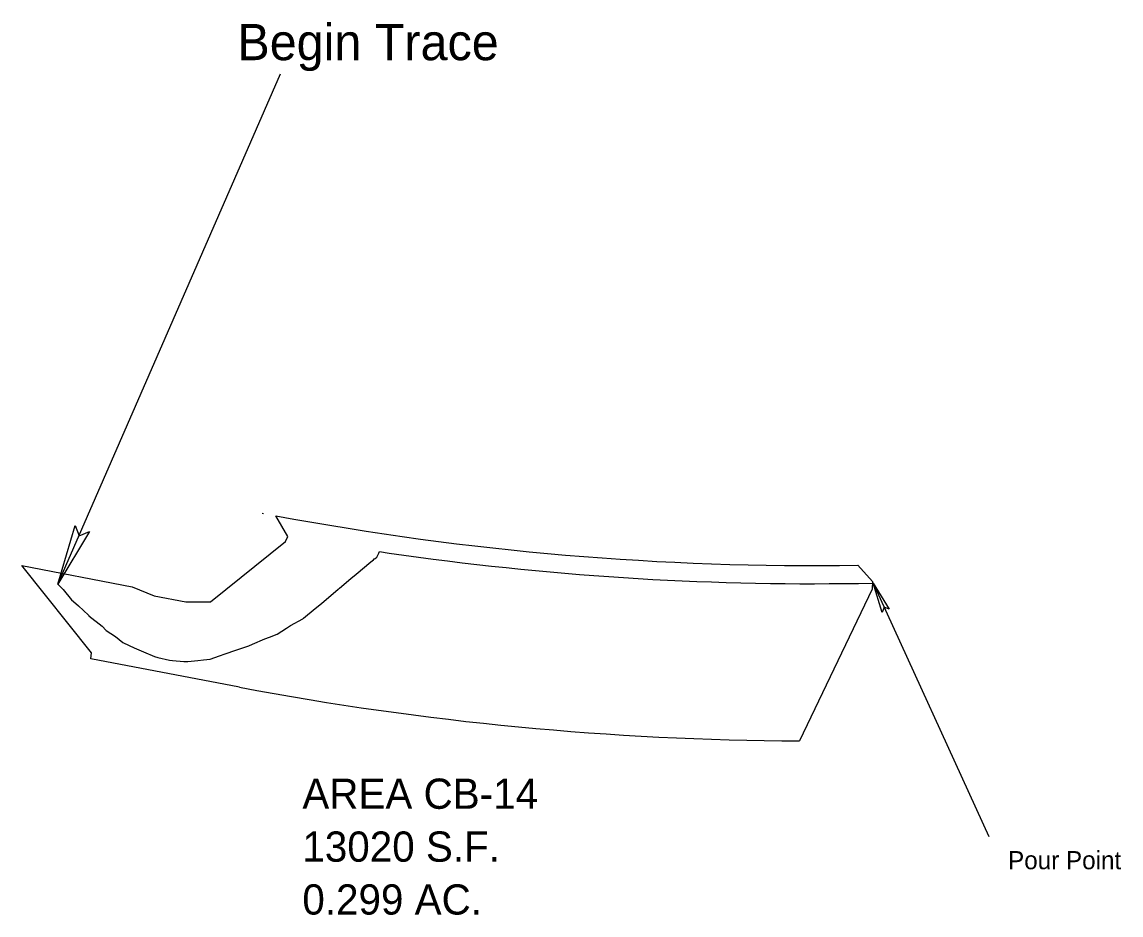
# Model space of a CAD drawing. Extents: x 3678 to 4042, y 2939 to 3235.
import ezdxf

# ---------------------------------------------------------------- set-up
doc = ezdxf.new("R2010")
doc.units = 0
for name, color, linetype in [('Default', 7, 'Continuous'), ('DESIGN - SCRATCH - User 1', 7, 'Continuous'), ('SURVEY - CENTERLINE - Preliminary', 7, 'Continuous'), ('SURVEY - CENTERLINE - Preliminary Text', 7, 'Continuous'), ('SURVEY - DRAINAGE - Area Shapes', 7, 'Continuous')]:
    doc.layers.add(name, color=color, linetype=linetype)

msp = doc.modelspace()

# ---------------------------------------------------------------- linework, layer by layer
at = {"layer": 'DESIGN - SCRATCH - User 1'}
msp.add_line((3960.18, 3049.18), (3998.4, 2965.35), dxfattribs=at)
msp.add_lwpolyline([(3960.18, 3049.18), (3965.48, 3040.55), (3963.81, 3041.22), (3963.16, 3039.49)], close=True, dxfattribs=at)
msp.add_lwpolyline([(3960.18, 3049.18), (3965.48, 3040.55), (3963.81, 3041.22), (3963.16, 3039.49), (3960.18, 3049.18)], dxfattribs=at)
at = {"layer": 'SURVEY - CENTERLINE - Preliminary'}
msp.add_lwpolyline([(3690.23, 3048.82), (3691.95, 3047.11), (3694.7, 3043.64), (3696.14, 3042.39), (3697.02, 3041.62), (3700.35, 3038.52), (3700.44, 3038.43), (3700.46, 3038.39), (3700.52, 3038.32), (3704.89, 3034.92), (3706.24, 3033.51), (3709.34, 3031.56), (3711.78, 3029.55), (3713.85, 3028.53), (3715.49, 3027.72), (3718.54, 3026.42), (3722.19, 3024.87), (3723.28, 3024.61), (3727.16, 3023.66), (3728.17, 3023.54), (3731.96, 3023.25), (3733.2, 3023.25), (3736.61, 3023.53), (3738.39, 3023.73), (3740.7, 3024), (3743.74, 3025.13), (3745.57, 3025.81), (3749.19, 3026.98), (3753.4, 3028.38), (3754.71, 3028.95), (3758.78, 3030.73), (3760.27, 3031.31), (3762.8, 3032.29), (3765.91, 3034.26), (3767.29, 3035.15), (3771.31, 3037.35), (3771.49, 3037.5), (3771.57, 3037.57), (3775.46, 3040.82), (3777.45, 3042.46), (3783.05, 3047.13), (3783.26, 3047.3), (3783.34, 3047.37), (3783.49, 3047.49), (3787.26, 3050.66), (3789.02, 3052.13), (3793.83, 3056.18), (3794.71, 3056.92), (3794.98, 3057.15), (3795, 3057.17), (3795.22, 3057.32), (3795.86, 3057.72), (3796.51, 3059.12), (3796.74, 3059.61), (3799.96, 3059.13), (3804.79, 3058.44), (3809.61, 3057.78), (3814.44, 3057.14), (3819.27, 3056.52), (3824.1, 3055.93), (3828.94, 3055.36), (3833.78, 3054.81), (3838.62, 3054.29), (3841.51, 3053.99), (3843.47, 3053.8), (3848.31, 3053.33), (3853.16, 3052.88), (3858.01, 3052.45), (3862.87, 3052.05), (3867.72, 3051.68), (3872.58, 3051.33), (3877.44, 3051), (3882.3, 3050.7), (3887.16, 3050.42), (3892.02, 3050.17), (3896.89, 3049.94), (3901.76, 3049.74), (3906.62, 3049.56), (3911.49, 3049.4), (3916.36, 3049.27), (3921.23, 3049.16), (3926.1, 3049.08), (3930.97, 3049.02), (3935.84, 3048.98), (3940.71, 3048.97), (3945.58, 3048.99), (3950.45, 3049.03), (3955.31, 3049.09), (3960.18, 3049.18)], dxfattribs=at)
at = {"layer": 'SURVEY - CENTERLINE - Preliminary Text'}
msp.add_line((3690.23, 3048.82), (3763.94, 3217.69), dxfattribs=at)
msp.add_lwpolyline([(3690.23, 3048.82), (3695.98, 3068.24), (3697.23, 3064.86), (3700.66, 3066.2)], close=True, dxfattribs=at)
msp.add_lwpolyline([(3690.23, 3048.82), (3695.98, 3068.24), (3697.23, 3064.86), (3700.66, 3066.2), (3690.23, 3048.82)], dxfattribs=at)
at = {"layer": 'SURVEY - DRAINAGE - Area Shapes'}
msp.add_line((3757.86, 3072.32), (3758.34, 3072.23), dxfattribs=at)
for points in [[(3678.34, 3054.95), (3714.79, 3047.98), (3722.08, 3044.94), (3732.55, 3042.98), (3740.78, 3043.01), (3765.61, 3062.9), (3766.32, 3064.63), (3762.43, 3071.45)], [(3701.11, 3024.13), (3701.39, 3026.11), (3678.34, 3054.95)], [(3955.02, 3055.09), (3959.96, 3049.67), (3959.8, 3047.17), (3935.77, 2996.98)], [(3750.4, 3014.69), (3701.11, 3024.13)]]:
    msp.add_lwpolyline(points, dxfattribs=at)
for radius, start, end in [(968, 259.41305, 270.87255), (1026.01, 259.3352, 269.74803)]:
    msp.add_arc((3940.28, 4022.98), radius, start, end, dxfattribs=at)

# ---------------------------------------------------------------- texts
at = {"layer": 'Default'}
for s, p in [('AREA CB-14', (3771.17, 2974.49)), ('13020 S.F.', (3771.17, 2956.99)), ('0.299 AC.', (3771.17, 2939.49))]:
    msp.add_text(s, height=10, dxfattribs=at).set_placement(p)
at = {"layer": 'DESIGN - SCRATCH - User 1'}
msp.add_text('Pour Point', height=6, dxfattribs=at).set_placement((4004.8, 2954.49))
at = {"layer": 'SURVEY - CENTERLINE - Preliminary Text'}
msp.add_text('Begin Trace ', height=12, dxfattribs=at).set_placement((3749.66, 3222.2))

doc.saveas('drawing.dxf')
